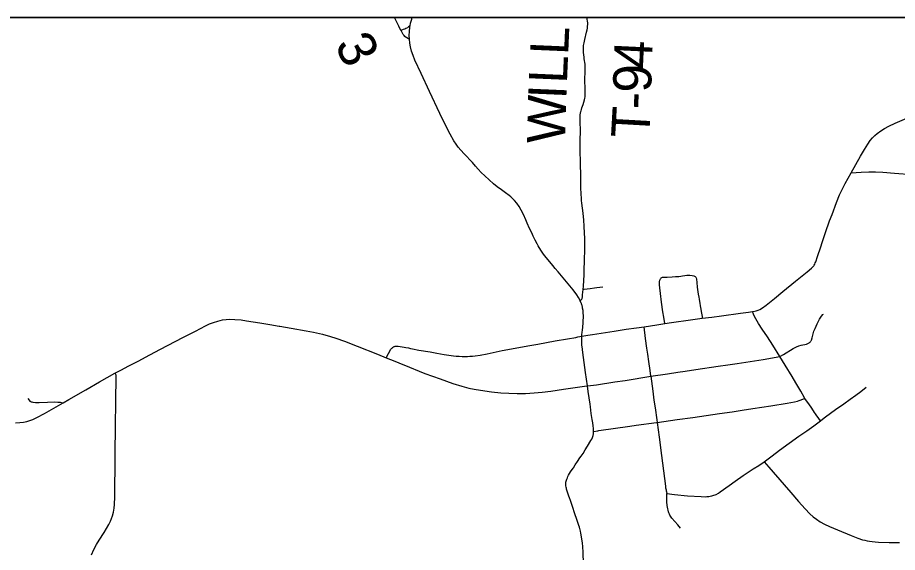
# Model space of a CAD drawing. Extents: x 0 to 191, y 0 to 55.
# Drawn here: x 20.353 to 22.317, y 18.776 to 19.97 of the extents above; entities that cross this region are included whole.
import ezdxf

# ---------------------------------------------------------------- set-up
doc = ezdxf.new("R2010")
doc.units = 0
for name, color, linetype in [('GM_X_City_Street', 7, 'Continuous'), ('GM_X_County_Road', 7, 'Continuous'), ('GM_X_State_Route', 7, 'Continuous'), ('GM_X_Township_Road', 7, 'Continuous'), ('GM_X_Township_Road_Text', 7, 'Continuous'), ('GM_X_Township_Text', 7, 'Continuous'), ('SH_Data', 7, 'Continuous')]:
    doc.layers.add(name, color=color, linetype=linetype)

msp = doc.modelspace()

# ---------------------------------------------------------------- linework, layer by layer
at = {"layer": 'GM_X_City_Street'}
for points in [[(21.6092, 19.3376), (21.6105, 19.339), (21.6112, 19.3399), (21.6118, 19.3408), (21.6124, 19.3416), (21.6132, 19.3432), (21.6137, 19.3445), (21.6139, 19.346), (21.6142, 19.3483), (21.6144, 19.351), (21.6155, 19.3632), (21.6161, 19.3701), (21.6177, 19.3955), (21.6182, 19.4091), (21.6185, 19.4246), (21.6186, 19.431), (21.6191, 19.4494), (21.6194, 19.4649), (21.6193, 19.4777), (21.6187, 19.4886), (21.618, 19.5041), (21.6173, 19.5178), (21.6154, 19.5334), (21.6131, 19.5554), (21.6123, 19.5618), (21.6109, 19.5812), (21.6105, 19.5857), (21.6104, 19.5867), (21.6102, 19.5932), (21.6102, 19.6044), (21.6104, 19.6117), (21.6105, 19.6163), (21.6105, 19.6199), (21.6103, 19.625), (21.6103, 19.6285), (21.6101, 19.632), (21.61, 19.6346), (21.6097, 19.6424)], [(21.752, 19.2796), (21.7799, 19.2843), (21.7982, 19.2868), (21.813, 19.2891), (21.8555, 19.295), (21.8816, 19.2986), (21.9026, 19.3015), (21.9247, 19.3044), (21.9672, 19.3098), (21.9847, 19.3121), (21.9933, 19.3135), (21.9948, 19.3137), (22.002, 19.3152), (22.0062, 19.3166), (22.0103, 19.3186), (22.0157, 19.3219), (22.0238, 19.328), (22.0426, 19.3432), (22.0614, 19.3586), (22.0897, 19.3814), (22.1159, 19.4022), (22.1257, 19.4107), (22.1277, 19.4127), (22.1294, 19.4146), (22.1305, 19.4161), (22.1314, 19.4175), (22.1325, 19.4198), (22.1337, 19.4222), (22.1347, 19.4247), (22.1388, 19.4363), (22.1459, 19.4584), (22.1491, 19.4681), (22.1564, 19.4903), (22.1654, 19.5158), (22.1711, 19.5306), (22.1811, 19.5567), (22.1881, 19.574), (22.1936, 19.5859), (22.2005, 19.5991), (22.2141, 19.6236)], [(22.2141, 19.6236), (22.2365, 19.6249), (22.2533, 19.6256), (22.2682, 19.6254), (22.2849, 19.6246), (22.3108, 19.6227), (22.3498, 19.6196), (22.358, 19.6188)], [(21.7982, 19.2868), (21.7965, 19.2969), (21.7929, 19.3176), (21.7919, 19.3244), (21.7905, 19.3348), (21.7882, 19.3538), (21.7867, 19.3669), (21.7863, 19.3734), (21.7862, 19.3758), (21.7862, 19.3781), (21.7862, 19.3798), (21.7863, 19.3815), (21.7865, 19.3828), (21.7869, 19.3841), (21.7873, 19.3854), (21.7881, 19.3867), (21.7889, 19.3877), (21.7899, 19.3886), (21.7913, 19.3895), (21.7929, 19.3901), (21.7956, 19.3904), (21.803, 19.3907), (21.8142, 19.3911), (21.8216, 19.3916), (21.829, 19.3922), (21.8336, 19.3928), (21.8377, 19.3936), (21.8427, 19.3943), (21.8473, 19.3946), (21.8538, 19.3946), (21.8593, 19.394), (21.8628, 19.3933), (21.8645, 19.3927), (21.866, 19.3917), (21.8671, 19.3904), (21.8679, 19.3889), (21.8686, 19.3863), (21.8694, 19.3789), (21.8704, 19.3684), (21.8726, 19.3523), (21.8736, 19.3459), (21.8743, 19.3413), (21.8751, 19.3362), (21.8759, 19.3321), (21.8772, 19.3262), (21.8785, 19.3187), (21.8794, 19.3139), (21.8805, 19.3066), (21.881, 19.3029), (21.8816, 19.2986)], [(21.6155, 19.3632), (21.618, 19.3635), (21.6317, 19.3652), (21.6409, 19.3664), (21.6464, 19.3671), (21.6529, 19.3679), (21.6596, 19.3687)], [(22.1451, 19.0696), (22.1415, 19.0751), (22.136, 19.0836), (22.1345, 19.0857), (22.1324, 19.0888), (22.1261, 19.098), (22.1191, 19.1078), (22.1121, 19.1176), (22.1107, 19.1198), (22.1095, 19.1215), (22.1015, 19.1362), (22.0907, 19.1547), (22.082, 19.1689), (22.0664, 19.1943), (22.0548, 19.2132), (22.0392, 19.2388), (22.0271, 19.2575), (22.0155, 19.2744), (22.0074, 19.2868), (22.0013, 19.2972), (21.9984, 19.303), (21.9959, 19.3081), (21.9933, 19.3135)], [(22.0548, 19.2132), (22.0626, 19.218), (22.0841, 19.2312), (22.0915, 19.2351), (22.0967, 19.2372), (22.1021, 19.2387), (22.114, 19.2412), (22.1158, 19.2417), (22.1175, 19.2424), (22.1189, 19.2431), (22.12, 19.2438), (22.1211, 19.2447), (22.1221, 19.2456), (22.1229, 19.2466), (22.1238, 19.2478), (22.1245, 19.2489), (22.1251, 19.2502), (22.1266, 19.2547), (22.1309, 19.27), (22.1333, 19.2761), (22.1377, 19.2863), (22.1435, 19.297), (22.1475, 19.3033), (22.1505, 19.3069), (22.1518, 19.3082)], [(21.2162, 19.2339), (21.22, 19.2333), (21.2256, 19.2324), (21.2302, 19.2315), (21.2351, 19.2305), (21.2487, 19.2278), (21.2744, 19.2235), (21.289, 19.2207), (21.3055, 19.218), (21.3159, 19.2163), (21.3266, 19.215), (21.3322, 19.2145), (21.3387, 19.214), (21.3459, 19.2137), (21.3526, 19.2135), (21.3573, 19.2135), (21.3628, 19.2138), (21.3685, 19.2142), (21.3749, 19.2149), (21.386, 19.2165), (21.4015, 19.2195), (21.4352, 19.2265), (21.4718, 19.2335), (21.492, 19.2372), (21.5149, 19.241), (21.5534, 19.2482), (21.581, 19.2527), (21.5992, 19.2561), (21.6037, 19.2571), (21.6126, 19.2591), (21.6258, 19.2613), (21.6363, 19.2627), (21.6851, 19.27), (21.7118, 19.2742), (21.7349, 19.2773), (21.752, 19.2796)], [(21.7666, 19.1697), (21.7652, 19.1823), (21.762, 19.2026), (21.7597, 19.2184), (21.7578, 19.2322), (21.7551, 19.2535), (21.752, 19.2796)], [(21.7666, 19.1697), (21.8037, 19.1747), (21.8268, 19.1783), (21.8434, 19.1807), (21.8674, 19.1841), (21.9172, 19.1915), (21.9384, 19.1948), (21.9596, 19.1979), (22.0177, 19.2067), (22.0548, 19.2132)], [(22.0199, 18.9782), (22.0379, 18.9919), (22.0541, 19.0043), (22.0758, 19.0203), (22.097, 19.0355), (22.1147, 19.0476), (22.1308, 19.0586), (22.1451, 19.0696), (22.1463, 19.0705), (22.1567, 19.0784), (22.1792, 19.0948), (22.1972, 19.1081), (22.2116, 19.1183), (22.2246, 19.1273), (22.2357, 19.1355), (22.2474, 19.1448)], [(21.639, 19.0463), (21.6487, 19.0478), (21.6505, 19.048), (21.7202, 19.0582), (21.7343, 19.0602), (21.7796, 19.0662), (21.7807, 19.0663), (21.8258, 19.0727), (21.8607, 19.0776), (21.9198, 19.086), (21.9484, 19.0902), (21.9705, 19.0935), (21.9944, 19.0972), (22.0345, 19.1032), (22.0708, 19.1094), (22.0877, 19.1125), (22.0939, 19.1139), (22.0975, 19.1149), (22.1026, 19.1168), (22.1075, 19.1186), (22.1107, 19.1198)], [(21.8331, 18.8306), (21.8269, 18.8375), (21.8135, 18.8528), (21.8118, 18.855), (21.8103, 18.8573), (21.8091, 18.8594), (21.8081, 18.8614), (21.8069, 18.8643), (21.8061, 18.8666), (21.8051, 18.8702), (21.8044, 18.8738), (21.8037, 18.8774), (21.8032, 18.8812), (21.8025, 18.8893), (21.8024, 18.8966), (21.8022, 18.9078)]]:
    msp.add_lwpolyline(points, dxfattribs=at)
at = {"layer": 'GM_X_County_Road'}
for points in [[(22.2141, 19.6236), (22.2346, 19.6604), (22.2434, 19.6757), (22.2508, 19.6875), (22.2563, 19.6951), (22.2615, 19.7016), (22.2668, 19.7069), (22.2717, 19.7111), (22.2801, 19.717), (22.288, 19.7219), (22.2978, 19.7272), (22.3122, 19.7339), (22.343, 19.7472)], [(20.5186, 18.7706), (20.5239, 18.7824), (20.5298, 18.794), (20.5354, 18.8036), (20.5465, 18.8208), (20.5569, 18.8385), (20.5609, 18.846), (20.5634, 18.8521), (20.5652, 18.8575), (20.5672, 18.8658), (20.5687, 18.8751), (20.5695, 18.8835), (20.5702, 18.9004), (20.5703, 18.9237), (20.5705, 18.9339), (20.5709, 18.9553), (20.5709, 18.9787), (20.571, 18.9908), (20.5712, 19.0168), (20.5717, 19.0373), (20.5718, 19.0447), (20.5723, 19.0755), (20.5726, 19.095), (20.5729, 19.1314), (20.5733, 19.15), (20.5733, 19.1584), (20.5735, 19.166), (20.5735, 19.1687), (20.5732, 19.1715), (20.5728, 19.1731), (20.5716, 19.1747), (20.5707, 19.1759)]]:
    msp.add_lwpolyline(points, dxfattribs=at)
at = {"layer": 'GM_X_State_Route'}
msp.add_line((21.7799, 19.0723), (21.7807, 19.0663), dxfattribs=at)
for points in [[(21.3684, 19.6463), (21.3501, 19.6656), (21.3424, 19.6737), (21.337, 19.6803), (21.3321, 19.6871), (21.327, 19.695), (21.3187, 19.7097), (21.3093, 19.728), (21.2959, 19.7557), (21.2729, 19.8046), (21.2539, 19.8451), (21.2404, 19.8748), (21.2362, 19.8852), (21.2328, 19.895), (21.2304, 19.9041), (21.2288, 19.9125), (21.2278, 19.9217), (21.2275, 19.9294), (21.2278, 19.9388), (21.2288, 19.9482), (21.2293, 19.951), (21.2305, 19.9574), (21.2331, 19.9665), (21.2342, 19.9697)], [(21.6135, 19.267), (21.6143, 19.2732), (21.6148, 19.2778), (21.6151, 19.2817), (21.6155, 19.2856), (21.6159, 19.2909), (21.616, 19.2945), (21.6163, 19.2996), (21.6163, 19.3022), (21.6162, 19.3056), (21.616, 19.3093), (21.6159, 19.3116), (21.6157, 19.3139), (21.6156, 19.3153), (21.6154, 19.3166), (21.6152, 19.3178), (21.615, 19.3191), (21.6145, 19.3215), (21.6143, 19.3227), (21.614, 19.3239), (21.6135, 19.3261), (21.6133, 19.3273), (21.6129, 19.3284), (21.6126, 19.3294), (21.6123, 19.3304), (21.6119, 19.3315), (21.6115, 19.3326), (21.6092, 19.3376), (21.6081, 19.34), (21.6056, 19.3447), (21.6017, 19.3509), (21.5934, 19.362), (21.5823, 19.3757), (21.5673, 19.3936), (21.5601, 19.4021), (21.5536, 19.41), (21.5482, 19.4163), (21.5447, 19.4205), (21.5407, 19.4254), (21.5378, 19.4289), (21.5334, 19.4343), (21.5275, 19.4417), (21.5256, 19.4443), (21.5211, 19.451), (21.5153, 19.4605), (21.5131, 19.4646), (21.5086, 19.4728), (21.5042, 19.4821), (21.5008, 19.4897), (21.4959, 19.4994), (21.4904, 19.5113), (21.4876, 19.5182), (21.4825, 19.5301), (21.4774, 19.54), (21.4727, 19.548), (21.4674, 19.5555), (21.4622, 19.5619), (21.4573, 19.5671), (21.4546, 19.5694), (21.4505, 19.5728), (21.4426, 19.5788), (21.4335, 19.585), (21.4236, 19.5921), (21.4156, 19.5985), (21.4058, 19.6073), (21.3963, 19.6163), (21.3884, 19.6242), (21.3814, 19.6317), (21.3751, 19.6384), (21.3684, 19.6463)], [(20.349, 19.0656), (20.3584, 19.0659), (20.3669, 19.0669), (20.3743, 19.0685), (20.3806, 19.0704), (20.3877, 19.0731), (20.3962, 19.077), (20.4135, 19.0863), (20.4551, 19.1101), (20.4677, 19.1173), (20.5057, 19.1391), (20.5364, 19.1566), (20.5707, 19.1759), (20.5852, 19.184), (20.5999, 19.1919), (20.624, 19.2041), (20.6389, 19.2118), (20.6709, 19.2291), (20.7238, 19.2565), (20.7503, 19.2703), (20.7726, 19.2818), (20.7818, 19.2861), (20.7904, 19.2894), (20.8001, 19.2924), (20.8109, 19.2949), (20.8191, 19.2963), (20.8254, 19.2966), (20.8384, 19.2961), (20.8522, 19.2949), (20.8642, 19.2933), (20.8941, 19.2884), (20.9167, 19.2846), (20.9374, 19.2812)], [(20.9374, 19.2812), (20.9389, 19.2809), (20.9638, 19.2768), (20.9977, 19.2709), (21.0141, 19.2676), (21.034, 19.2629), (21.0519, 19.258), (21.0634, 19.2543), (21.0827, 19.2475), (21.1113, 19.2362), (21.1564, 19.2185), (21.1762, 19.2107), (21.1951, 19.203), (21.213, 19.1955), (21.2152, 19.1947)], [(21.6133, 19.2359), (21.6131, 19.2373), (21.6129, 19.24), (21.6126, 19.2432), (21.6124, 19.2469), (21.6124, 19.2498), (21.6124, 19.253), (21.6125, 19.256), (21.6125, 19.2577), (21.6126, 19.2591), (21.6129, 19.2624), (21.6135, 19.267)], [(21.6359, 19.0727), (21.6338, 19.0863), (21.6321, 19.101), (21.6311, 19.1074), (21.6272, 19.135), (21.6252, 19.1483), (21.6232, 19.1627), (21.6212, 19.1775), (21.6148, 19.2227), (21.6133, 19.2359)], [(21.2152, 19.1947), (21.2626, 19.1758), (21.2967, 19.1632), (21.325, 19.1535), (21.3446, 19.1474), (21.3609, 19.143), (21.3727, 19.1404), (21.3866, 19.138), (21.4115, 19.1346), (21.432, 19.1324), (21.4497, 19.1313), (21.4684, 19.1309), (21.4746, 19.131)], [(21.6252, 19.1483), (21.6452, 19.1505), (21.6866, 19.1568), (21.7097, 19.1599), (21.7666, 19.1697)], [(21.7666, 19.1697), (21.7695, 19.1473), (21.7711, 19.1358), (21.7738, 19.1156), (21.7761, 19.0991), (21.7799, 19.0723)], [(21.4746, 19.131), (21.4871, 19.1312), (21.5067, 19.1323), (21.5244, 19.1339), (21.5438, 19.1364), (21.5715, 19.1404), (21.6185, 19.1473), (21.6252, 19.1483)], [(21.5939, 18.9652), (21.5981, 18.9713), (21.6032, 18.9792), (21.6086, 18.987), (21.6114, 18.9911), (21.6154, 18.9973), (21.6204, 19.0053), (21.6254, 19.0133), (21.6331, 19.0257), (21.6349, 19.0291), (21.6363, 19.0323), (21.6373, 19.0348), (21.6381, 19.0372), (21.6388, 19.0406), (21.639, 19.0428), (21.639, 19.0451), (21.639, 19.0463), (21.6388, 19.0489), (21.6386, 19.0524), (21.6379, 19.059), (21.637, 19.0652), (21.6359, 19.0727)], [(21.7807, 19.0663), (21.785, 19.0335), (21.7903, 18.9928), (21.7992, 18.9243), (21.7995, 18.9224), (21.7997, 18.9206), (21.8001, 18.9183)], [(21.8022, 18.9078), (21.8198, 18.9051), (21.8486, 18.9026), (21.8793, 18.9008), (21.8879, 18.9006), (21.8916, 18.9008), (21.8959, 18.9012), (21.8995, 18.9018), (21.9029, 18.9025), (21.9054, 18.9032), (21.9075, 18.9039), (21.91, 18.9047), (21.9122, 18.9057), (21.9178, 18.9087), (21.9218, 18.9113), (21.9416, 18.9253), (21.9552, 18.9351), (21.9726, 18.9475), (21.9949, 18.9626), (22.0075, 18.9705), (22.0199, 18.9782)], [(22.0199, 18.9782), (22.0299, 18.9667), (22.0646, 18.9267), (22.0793, 18.9099), (22.0962, 18.8901), (22.1109, 18.8735), (22.1218, 18.8623), (22.1293, 18.8556), (22.1365, 18.8501), (22.145, 18.8447), (22.1547, 18.8394), (22.1655, 18.8341), (22.1833, 18.8265), (22.2141, 18.8137), (22.2287, 18.808), (22.2392, 18.8045), (22.244, 18.8033), (22.2498, 18.8019), (22.255, 18.801), (22.2607, 18.8002), (22.2677, 18.7996), (22.2745, 18.7992), (22.2987, 18.7985), (22.3219, 18.798)], [(21.6166, 18.7506), (21.6159, 18.7767), (21.6152, 18.7888), (21.6141, 18.7979), (21.6129, 18.8059), (21.612, 18.8108), (21.6105, 18.8188), (21.6096, 18.8239), (21.609, 18.8268), (21.6083, 18.8295), (21.6079, 18.8311), (21.6074, 18.8327), (21.6061, 18.8365), (21.6023, 18.8471), (21.5964, 18.8647), (21.5927, 18.8761), (21.5903, 18.8831), (21.5874, 18.8918), (21.5853, 18.8978), (21.584, 18.9017), (21.5794, 18.9148), (21.5788, 18.9172), (21.5782, 18.9194), (21.5777, 18.9221), (21.5773, 18.9248), (21.5771, 18.9268), (21.5769, 18.9288), (21.577, 18.9307), (21.5772, 18.9328), (21.5776, 18.9349), (21.5784, 18.9374), (21.5792, 18.9396), (21.5804, 18.9426), (21.5818, 18.9456), (21.5833, 18.9487), (21.5853, 18.9522), (21.5877, 18.956), (21.5931, 18.964), (21.5939, 18.9652)], [(21.8001, 18.9183), (21.8006, 18.9156), (21.801, 18.9138), (21.8015, 18.9111), (21.8022, 18.9078)]]:
    msp.add_lwpolyline(points, dxfattribs=at)
at = {"layer": 'GM_X_Township_Road'}
for points in [[(21.2091, 19.941), (21.204, 19.9508), (21.1952, 19.9683), (21.1946, 19.9697)], [(21.2293, 19.951), (21.2259, 19.9488), (21.2233, 19.9471), (21.2201, 19.9453), (21.2177, 19.9442), (21.2142, 19.943), (21.2091, 19.941)], [(21.6097, 19.6424), (21.6096, 19.6478), (21.609, 19.6718), (21.6089, 19.676), (21.6089, 19.681), (21.6091, 19.6884), (21.6092, 19.6938), (21.6093, 19.7012), (21.6095, 19.7113), (21.6095, 19.7187), (21.6095, 19.7215), (21.6095, 19.7251), (21.6092, 19.7295), (21.6091, 19.7335), (21.6089, 19.738), (21.6089, 19.7424), (21.609, 19.7459), (21.6091, 19.749), (21.6094, 19.7526), (21.6098, 19.7562), (21.6104, 19.7598), (21.611, 19.7619), (21.6117, 19.7644), (21.613, 19.7685), (21.6155, 19.7761), (21.6171, 19.7811), (21.6187, 19.7859), (21.6194, 19.7896), (21.62, 19.7932), (21.6202, 19.7968), (21.6203, 19.8007), (21.6199, 19.8156), (21.6197, 19.8249), (21.6197, 19.8333), (21.6202, 19.8482), (21.6205, 19.8565), (21.6203, 19.862), (21.6199, 19.8656), (21.6183, 19.8773), (21.6178, 19.8814), (21.6172, 19.8864), (21.6167, 19.8915), (21.6164, 19.8963), (21.6164, 19.9007), (21.6166, 19.9043), (21.6168, 19.9072), (21.6178, 19.9136), (21.6194, 19.9208), (21.6235, 19.937), (21.6247, 19.9422), (21.6253, 19.9462), (21.6257, 19.9507), (21.6259, 19.9545), (21.6259, 19.9583), (21.6256, 19.9619), (21.6249, 19.9665), (21.6243, 19.9697)], [(21.2278, 19.9217), (21.226, 19.9226), (21.222, 19.9246), (21.2204, 19.9256), (21.218, 19.9272), (21.2159, 19.9294), (21.2141, 19.932), (21.21, 19.9393), (21.2091, 19.941)], [(21.1762, 19.2107), (21.1868, 19.2294), (21.188, 19.2309), (21.1893, 19.2322), (21.1903, 19.2332), (21.1914, 19.234), (21.1926, 19.2348), (21.1938, 19.2354), (21.195, 19.2358), (21.1965, 19.2363), (21.1977, 19.2365), (21.1992, 19.2366), (21.201, 19.2365), (21.203, 19.2363), (21.2162, 19.2339)], [(20.3765, 19.12), (20.3792, 19.1162), (20.3811, 19.1141), (20.3834, 19.1126), (20.3851, 19.1119), (20.3878, 19.1113), (20.3933, 19.1108), (20.4017, 19.1107), (20.4203, 19.1115), (20.4351, 19.112), (20.4431, 19.1116), (20.4483, 19.1112), (20.454, 19.1103), (20.4551, 19.1101)]]:
    msp.add_lwpolyline(points, dxfattribs=at)
at = {"layer": 'GM_X_Township_Text'}
msp.add_lwpolyline([(26.9454, 19.9697), (19.2489, 19.9697), (19.2489, 17.3861)], dxfattribs=at)
at = {"layer": 'SH_Data'}
msp.add_line((19.2489, 19.9697), (29.4489, 19.9697), dxfattribs=at)

# ---------------------------------------------------------------- texts
at = {"layer": 'GM_X_Township_Road_Text'}
for s, rotation, p in [('3', 296.8694, (21.0598, 19.9092)), ('L', 87.5437, (21.5822, 19.8851)), ('4', 87.2774, (21.7682, 19.8537)), ('L', 87.5436, (21.5794, 19.8214)), ('9', 89.6631, (21.7679, 19.8022)), ('W', 88.4671, (21.5753, 19.688)), ('I', 87.5715, (21.578, 19.7864)), ('-', 87.7699, (21.7664, 19.7641)), ('T', 86.784, (21.7628, 19.6989))]:
    msp.add_text(s, height=0.0852, rotation=rotation, dxfattribs=at).set_placement(p)

doc.saveas('drawing.dxf')
